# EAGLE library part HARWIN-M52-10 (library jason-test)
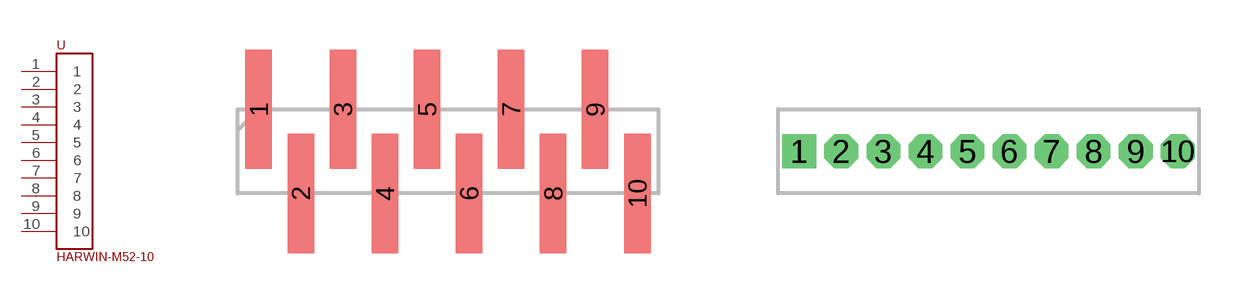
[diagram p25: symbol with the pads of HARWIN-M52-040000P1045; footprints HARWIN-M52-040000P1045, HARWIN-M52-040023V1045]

Designator prefix -

## HARWIN-M52-10SMD  [HARWIN-M52-040000P1045]
1  1
2  2
3  3
4  4
5  5
6  6
7  7
8  8
9  9
10  10

## HARWIN-M52-10PTH  [HARWIN-M52-040023V1045]
Pads as for HARWIN-M52-040000P1045

## Footprint HARWIN-M52-040000P1045 (pad centres in mm)
smd 0.8 x 3.6: 1 -5.715,1.27; 2 -4.445,-1.27; 3 -3.175,1.27; 4 -1.905,-1.27; 5 -0.635,1.27; 6 0.635,-1.27; 7 1.905,1.27; 8 3.175,-1.27; 9 4.445,1.27; 10 5.715,-1.27

## Footprint HARWIN-M52-040023V1045 (pad centres in mm)
drill 0.5 pad 1.016 square: 1 -5.715,0
drill 0.5 pad 1.016 octagon: 2 -4.445,0; 3 -3.175,0; 4 -1.905,0; 5 -0.635,0; 6 0.635,0; 7 1.905,0; 8 3.175,0; 9 4.445,0; 10 5.715,0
